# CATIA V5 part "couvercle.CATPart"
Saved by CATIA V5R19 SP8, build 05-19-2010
Part number: couvercle
Bounding box of the stored display mesh (mm): x -120 to 120, y -120 to 120, z 0 to 10
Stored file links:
  G:\EU_thinkMotion\CFAO_2010\St2M_groupe2\St2M_groupe2\npeyre\npeyre\couvercle.CATPart
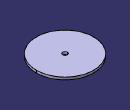
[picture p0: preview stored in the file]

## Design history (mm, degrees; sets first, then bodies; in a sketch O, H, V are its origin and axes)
Parameters
  `diametre alesage sortie vers generateur` = 10 mm
  `diametre couvercle` = 240 mm
  `epaisseur couvercle` = 10 mm
Body1 (main body)
  Sketch1 on xy-plane, origin (0, 0, 0), H (1, 0, 0), V (0, 1, 0)
    circle A1 centre (0, 0) radius 10
    circle A2 centre (0, 0) radius 120
    point P1 (0, 0)
    radius A2 = 120 {= `diametre couvercle` /2}
    radius A1 = 10 {= `diametre alesage sortie vers generateur`}
    coincidence: P1 O
    concentricity: A1 P1
  Pad1: profile Sketch1, direction (0, 0, 1), length 10 {= `epaisseur couvercle`}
